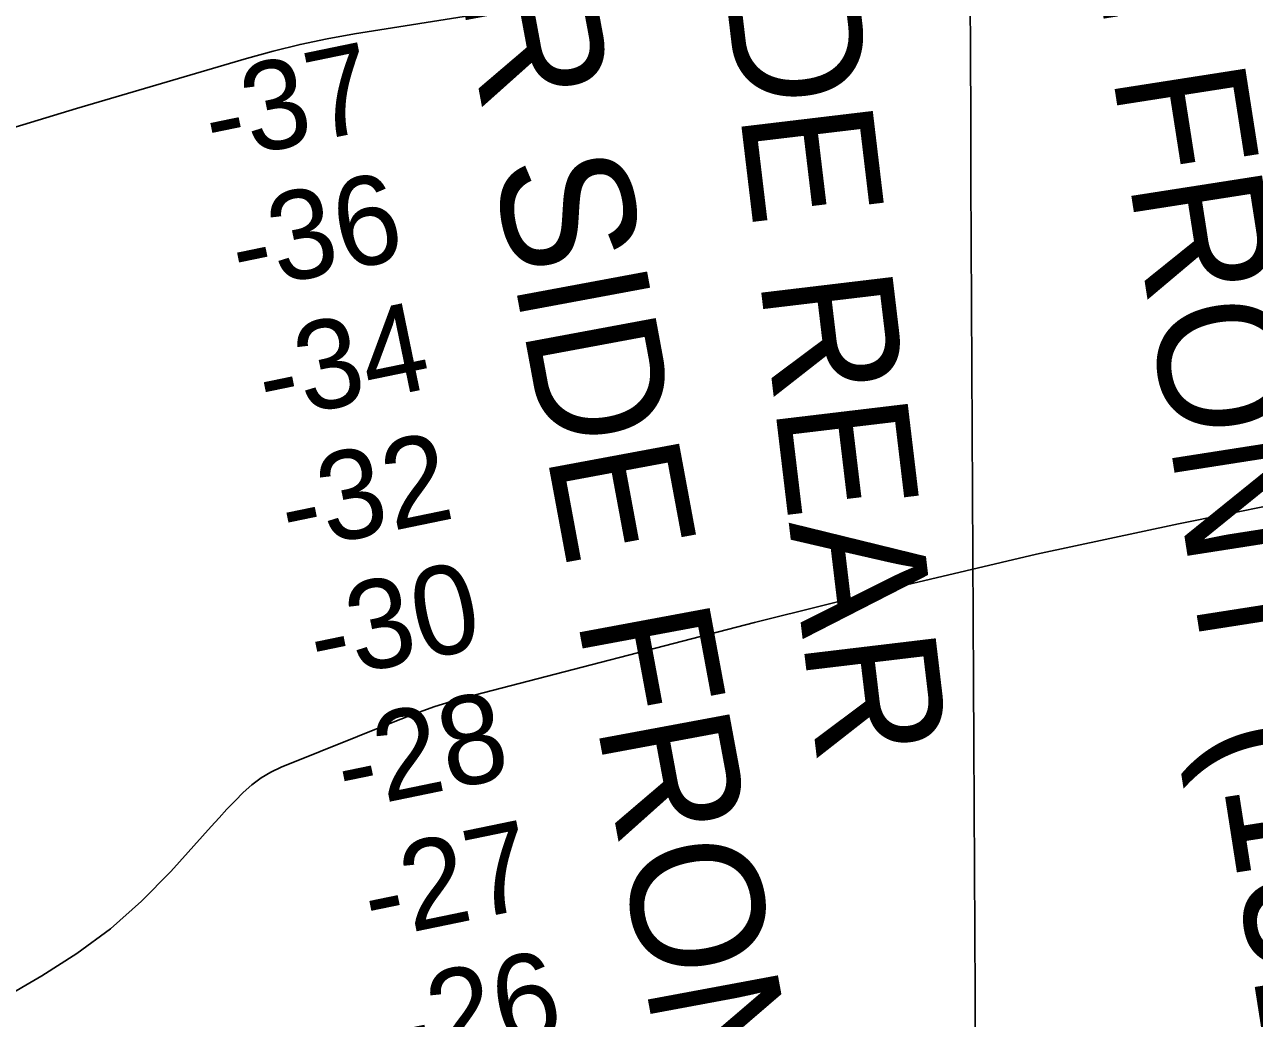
# Model space of a CAD drawing. Extents: x 3445503 to 3483459, y 540493 to 566012.
# Drawn here: x 3459462 to 3460392, y 550038 to 550789 of the extents above; entities that cross this region are included whole.
import ezdxf

# ---------------------------------------------------------------- set-up
doc = ezdxf.new("R2010")
doc.units = 0
for name, color, linetype in [('V-CHAN-NAID', 7, 'Continuous'), ('V-GRID-MAJR', 7, 'Continuous'), ('V-RIVR-EDGE', 7, 'Continuous'), ('V-RIVR-RANG', 7, 'Continuous'), ('V-TOPO-DPTH', 7, 'Continuous'), ('V-TOPO-MINR', 7, 'Continuous')]:
    doc.layers.add(name, color=color, linetype=linetype)

msp = doc.modelspace()

# ---------------------------------------------------------------- linework, layer by layer
at = {"layer": 'V-GRID-MAJR'}
msp.add_spline([(3460200.663, 545938.965), (3460170.705, 551996.853), (3460140.731, 558057.825), (3460110.758, 564118.814), (3460110.7430000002, 564121.882)], degree=3, dxfattribs=at)
at = {"layer": 'V-RIVR-EDGE'}
msp.add_spline([(3461691.094660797, 550090.6249650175), (3461685.1789394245, 550088.2061703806), (3461682.0528512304, 550089.2567956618), (3461676.1543216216, 550093.7905942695), (3461669.897847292, 550094.1536965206), (3461662.245696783, 550092.4344591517), (3461650.0717819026, 550089.6835074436), (3461638.5888284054, 550085.1926882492), (3461634.052451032, 550078.251269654), (3461621.8613443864, 550068.5477247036), (3461600.981215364, 550059.5609287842), (3461578.709708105, 550050.2299415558), (3461554.0022144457, 550039.8620824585), (3461533.464557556, 550028.788648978), (3461518.844341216, 550020.8292694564), (3461501.789857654, 550012.5282773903), (3461491.349793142, 550008.0348794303), (3461484.3937615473, 550006.6615525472), (3461481.268532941, 550008.0598074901), (3461477.0952578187, 550007.3748632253), (3461469.4396689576, 550004.2651072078), (3461447.1587062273, 549991.1101936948), (3461439.5048365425, 549988.6956970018), (3461429.772065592, 549989.0673951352), (3461421.7757237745, 549988.7395360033), (3461411.688446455, 549986.3310564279), (3461391.512172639, 549980.8188379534), (3461375.1538079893, 549972.8637563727), (3461352.874564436, 549960.4041021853), (3461336.8595315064, 549950.7100127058), (3461318.7724740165, 549946.58315535), (3461308.695511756, 549948.3462317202), (3461291.3260628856, 549953.2560264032), (3461279.5075139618, 549953.6328820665), (3461264.555140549, 549951.9316960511), (3461242.29824629, 549948.5104130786), (3461221.077364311, 549942.3055140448), (3461196.3819048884, 549936.8044702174), (3461168.909706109, 549933.048451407), (3461154.2980856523, 549928.5653685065), (3461121.5968289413, 549918.9125392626), (3461097.9227687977, 549904.7181751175), (3461074.941389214, 549889.4792028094), (3461062.746844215, 549878.3851392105), (3461055.779637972, 549872.4926267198), (3461050.912822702, 549872.5046609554), (3461047.7944708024, 549876.6839531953), (3461040.5080013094, 549882.2640791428), (3461033.9038973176, 549882.6280409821), (3461022.0810504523, 549881.2667483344), (3461014.7808275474, 549881.2847996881), (3461005.4051417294, 549885.4795645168), (3460996.3719280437, 549887.5876917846), (3460985.5945489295, 549887.2667093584), (3460970.6421755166, 549885.5655233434), (3460956.391078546, 549886.2960257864), (3460942.4876112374, 549887.0256686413), (3460929.2759649, 549886.3630736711), (3460917.800747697, 549885.0009214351), (3460903.5470719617, 549884.6885348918), (3460887.1955840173, 549879.5144906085), (3460852.755319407, 549869.5183296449), (3460840.2286173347, 549864.6824595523), (3460821.1029688, 549862.2963292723), (3460795.699356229, 549851.5825596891), (3460790.471157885, 549846.0333789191), (3460788.726132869, 549843.2566395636), (3460784.89962782, 549842.2232060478), (3460781.4336462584, 549846.4033578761), (3460776.9178990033, 549847.805051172), (3460767.1842684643, 549847.8291196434), (3460736.221160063, 549838.1719924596), (3460692.04382656, 549826.8093813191), (3460656.9091622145, 549817.1625691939), (3460631.169094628, 549810.9688448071), (3460623.867152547, 549810.2916368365), (3460614.476853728, 549808.5766974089), (3460594.3048778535, 549804.802627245), (3460589.4286071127, 549800.9907351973), (3460582.117209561, 549796.4896009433), (3460575.150862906, 549790.9447181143), (3460546.6246004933, 549782.6720924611), (3460534.794017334, 549778.1821328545), (3460511.8453021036, 549776.1530877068), (3460498.637953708, 549777.2286410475), (3460487.861434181, 549777.2552882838), (3460473.6034605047, 549775.2047534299), (3460462.1205070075, 549770.7139342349), (3460451.331093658, 549765.5261365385), (3460445.0746193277, 549765.8892387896), (3460436.039686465, 549767.3021067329), (3460430.129122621, 549766.9690900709), (3460422.8237421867, 549764.9013634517), (3460399.859554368, 549756.6149843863), (3460376.5528944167, 549750.4152428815), (3460361.5884867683, 549743.8472415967), (3460324.3594485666, 549730.7292903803), (3460287.4780400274, 549717.6104795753), (3460234.9455603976, 549701.4016832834), (3460200.852065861, 549691.0570330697), (3460155.2850732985, 549680.0454899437), (3460083.2836134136, 549663.18957127), (3459984.5069332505, 549643.2711739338), (3459950.4220345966, 549636.4028203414), (3459904.151186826, 549621.9166997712), (3459887.4503500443, 549616.0482557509), (3459873.530550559, 549610.1729350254), (3459867.9530033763, 549603.9293545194), (3459852.6383873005, 549596.3193238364), (3459825.8485540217, 549587.3471409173), (3459815.4084895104, 549582.8537429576), (3459807.758058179, 549581.8297649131), (3459789.679596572, 549581.1792041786), (3459770.547930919, 549576.3596662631), (3459736.4630322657, 549569.4913126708), (3459697.162829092, 549562.2882232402), (3459681.50746006, 549557.460089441), (3459673.162628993, 549556.7854602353), (3459662.04105857, 549557.855856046), (3459646.397723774, 549557.8945375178), (3459629.702044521, 549554.1118714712), (3459606.389367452, 549545.4787223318), (3459575.0743314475, 549534.0843064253), (3459541.3310453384, 549524.7816856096), (3459499.941625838, 549516.19323506), (3459471.0737508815, 549510.3548766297), (3459449.8502901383, 549503.107088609), (3459421.32660649, 549495.8773519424), (3459395.9324493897, 549488.9875086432), (3459373.321908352, 549483.1336776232), (3459354.8786253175, 549475.5313832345), (3459342.7064296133, 549473.4756908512), (3459324.6210913, 549470.0440928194), (3459296.0956884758, 549462.1190968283), (3459240.4336822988, 549445.5704071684), (3459208.4216677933, 549433.4824511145), (3459176.059444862, 549420.352465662), (3459163.8786532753, 549414.8204766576), (3459142.316158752, 549411.0498448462), (3459129.447844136, 549408.6482419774), (3459115.879972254, 549404.510209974), (3459080.0517677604, 549395.5603763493), (3459049.784778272, 549386.2491596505), (3459013.611522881, 549378.3430746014), (3458998.650553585, 549373.1655919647), (3458977.427092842, 549365.9178039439), (3458951.3359572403, 549358.3344204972), (3458937.746595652, 549345.5056469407), (3458926.970076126, 549345.5322941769), (3458917.2407435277, 549347.2945109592), (3458911.678668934, 549347.3082643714), (3458881.4133986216, 549338.692306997), (3458872.3543972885, 549330.3715444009), (3458862.9615197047, 549327.613715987), (3458852.185000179, 549327.6403632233), (3458812.5165372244, 549312.0950214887), (3458799.2997333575, 549309.3466485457), (3458789.554068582, 549304.5039017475), (3458776.684034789, 549301.4070395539), (3458769.0113588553, 549300.6681868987)], degree=3, dxfattribs=at)
at = {"layer": 'V-TOPO-DPTH'}
for points in [[(3459416.9378179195, 550700.1609228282), (3459501.047127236, 550725.7273051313), (3459629.425667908, 550763.5634659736), (3459649.66669446, 550769.1036755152), (3459670.0272410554, 550774.1140285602), (3459690.567067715, 550778.3295968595), (3459711.226414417, 550782.0153086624), (3460275.769576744, 550871.4454573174)], [(3460275.769576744, 550871.4454573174), (3459711.226414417, 550782.0153086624), (3459690.567067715, 550778.3295968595), (3459670.0272410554, 550774.1140285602), (3459649.66669446, 550769.1036755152), (3459629.425667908, 550763.5634659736), (3459501.047127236, 550725.7273051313), (3459416.9378179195, 550700.1609228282)], [(3460441.753683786, 550433.6042500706), (3460334.145364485, 550411.8930689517), (3460226.843139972, 550388.8214959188), (3460120.000057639, 550363.7093350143), (3460013.463070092, 550337.2367821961), (3459801.6892553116, 550282.466781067), (3459786.7714647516, 550278.2942486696), (3459771.9806021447, 550273.7368118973), (3459757.3801314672, 550268.6020185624), (3459742.906588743, 550263.0823208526), (3459655.840863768, 550227.9035654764), (3459647.9667609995, 550224.1496725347), (3459640.4784239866, 550219.81384869), (3459633.568735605, 550214.6051284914), (3459627.0448129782, 550208.8144773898), (3459620.870651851, 550202.5246022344), (3459614.763770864, 550196.1710714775), (3459608.757810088, 550189.7220573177), (3459602.819129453, 550183.2093875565), (3459572.205604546, 550149.1007548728), (3459550.0495631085, 550126.6731168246), (3459526.638714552, 550105.7953929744), (3459501.3456553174, 550087.2425404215), (3459474.797788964, 550070.2396020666), (3459462.7402163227, 550063.3072987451), (3459435.04781259, 550047.1385886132)], [(3460441.753683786, 550433.6042500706), (3460334.145364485, 550411.8930689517), (3460226.843139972, 550388.8214959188), (3460120.000057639, 550363.7093350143), (3460013.463070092, 550337.2367821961), (3459801.6892553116, 550282.466781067), (3459786.7714647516, 550278.2942486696), (3459771.9806021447, 550273.7368118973), (3459757.3801314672, 550268.6020185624), (3459742.906588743, 550263.0823208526), (3459655.840863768, 550227.9035654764), (3459647.9667609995, 550224.1496725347), (3459640.4784239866, 550219.81384869), (3459633.568735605, 550214.6051284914), (3459627.0448129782, 550208.8144773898), (3459620.870651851, 550202.5246022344), (3459614.763770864, 550196.1710714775), (3459608.757810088, 550189.7220573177), (3459602.819129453, 550183.2093875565), (3459572.205604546, 550149.1007548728), (3459550.0495631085, 550126.6731168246), (3459526.638714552, 550105.7953929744), (3459501.3456553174, 550087.2425404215), (3459474.797788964, 550070.2396020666), (3459462.7402163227, 550063.3072987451), (3459435.04781259, 550047.1385886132)]]:
    msp.add_lwpolyline(points, dxfattribs=at)
at = {"layer": 'V-TOPO-MINR'}
for points in [[(3459416.9378179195, 550700.1609228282), (3459501.047127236, 550725.7273051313), (3459629.425667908, 550763.5634659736), (3459649.66669446, 550769.1036755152), (3459670.0272410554, 550774.1140285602), (3459690.567067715, 550778.3295968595), (3459711.226414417, 550782.0153086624), (3460275.769576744, 550871.4454573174)], [(3459435.04781259, 550047.1385886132), (3459462.7402163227, 550063.3072987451), (3459474.797788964, 550070.2396020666), (3459501.3456553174, 550087.2425404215), (3459526.638714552, 550105.7953929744), (3459550.0495631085, 550126.6731168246), (3459572.205604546, 550149.1007548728), (3459602.819129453, 550183.2093875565), (3459608.757810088, 550189.7220573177), (3459614.763770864, 550196.1710714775), (3459620.870651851, 550202.5246022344), (3459627.0448129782, 550208.8144773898), (3459633.568735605, 550214.6051284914), (3459640.4784239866, 550219.81384869), (3459647.9667609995, 550224.1496725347), (3459655.840863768, 550227.9035654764), (3459742.906588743, 550263.0823208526), (3459757.3801314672, 550268.6020185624), (3459771.9806021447, 550273.7368118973), (3459786.7714647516, 550278.2942486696), (3459801.6892553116, 550282.466781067), (3460013.463070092, 550337.2367821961), (3460120.000057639, 550363.7093350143), (3460226.843139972, 550388.8214959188), (3460334.145364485, 550411.8930689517), (3460441.753683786, 550433.6042500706)]]:
    msp.add_lwpolyline(points, dxfattribs=at)

# ---------------------------------------------------------------- texts
at = {"layer": 'V-CHAN-NAID'}
for s, height, rotation, p in [('LWR BELMONT RANGE UPR SIDE REAR', 100.00000199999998, 276.8095539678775, (3459756.6226747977, 552781.2154548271)), ('LWR BELMONT RANGE UPR SIDE FRONT (152.2)', 100.000002, 280.53449283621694, (3459477.2511466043, 552502.9467602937)), ('LWR BELMONT RANGE FRONT (152.2)', 100.000002, 278.8729088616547, (3460048.098091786, 552263.4570882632))]:
    msp.add_text(s, height=height, rotation=rotation, dxfattribs=at).set_placement(p)
at = {"layer": 'V-RIVR-RANG'}
for s, p in [('-37', (3459604.2577000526, 550684.8363402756)), ('-36', (3459624.475615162, 550586.9009818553)), ('-34', (3459644.6819624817, 550488.9642387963)), ('-32', (3459661.7871419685, 550390.3884124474)), ('-30', (3459683.543573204, 550292.7712110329)), ('-28', (3459704.2666151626, 550194.9399818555)), ('-27', (3459724.460394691, 550097.000854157)), ('-26', (3459744.6783098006, 549999.0664957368))]:
    msp.add_text(s, height=67.00000000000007, rotation=11.648055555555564, dxfattribs=at).set_placement(p)

doc.saveas('drawing.dxf')
